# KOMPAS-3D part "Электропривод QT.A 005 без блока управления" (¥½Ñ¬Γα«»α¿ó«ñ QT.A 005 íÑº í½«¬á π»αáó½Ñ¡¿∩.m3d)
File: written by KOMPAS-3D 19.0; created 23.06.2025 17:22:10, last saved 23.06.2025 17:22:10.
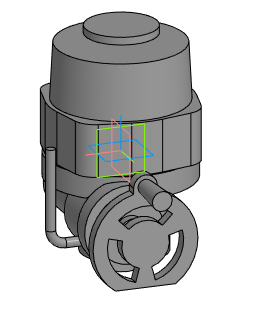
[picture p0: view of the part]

Document properties: Автор: Евгений; Полное имя файла: E:\Dendor Работа Сачек\3D для проектировщиков\3.5 Тип QT.А Электропривод\stp_Электропривод QT.A без блока управления\Электропривод QT.A 005 без блока управления.m3d

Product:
- Part/product: Электропривод QT.A 005 без блока управления

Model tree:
1. Операция без истории:1  (labels: Электропривод QT.A 005 без блока управления)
